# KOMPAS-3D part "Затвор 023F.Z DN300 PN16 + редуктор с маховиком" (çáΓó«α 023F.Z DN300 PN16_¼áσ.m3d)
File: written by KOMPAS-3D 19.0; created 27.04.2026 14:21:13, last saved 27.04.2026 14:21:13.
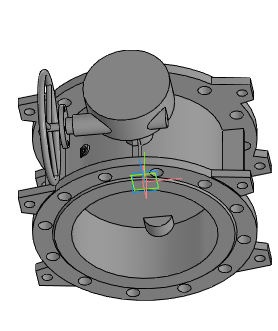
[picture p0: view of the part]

Document properties: Полное имя файла: ..\..\Затвор 023F.Z DN200-DN1600_с маховиком\Затвор 023F.Z DN300 PN16 + редуктор с маховиком.a3d

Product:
- Part/product: Затвор 023F.Z DN300 PN16 + редуктор с маховиком
    Масса: 99.7882

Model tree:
1. Операция без истории:1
